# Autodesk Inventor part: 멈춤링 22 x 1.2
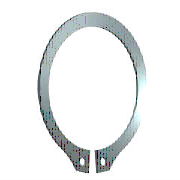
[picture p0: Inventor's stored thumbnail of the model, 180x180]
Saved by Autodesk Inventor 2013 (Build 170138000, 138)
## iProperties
IsCustomPart: 0
Company: 한국ATC센터
Created: 2014-07
Part Number: 멈춤링 22 x 1.2
Material: Steel, Mild
Description: 리테이닝 링(C형)
Document SubType Name: Modeling
Standard: KS B 1336
Designer: KYOUNG IL JANG
Standards Organization: KS
Language: ko-KR
Size Designation: 22 x 1.2
Categories: <MemberInstance><Categories><Category DisplayName="샤프트 부품" InternalName="7f7aeb1f-a693-4053-b835-cee3144e0d98" Mnemonic="SHFT"><Category DisplayName="써클립" Inter
Density: 1 g/cm^3
Author: KYOUNG IL JANG
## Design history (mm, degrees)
sketch "스케치1"
  geometry: L1 (-6, 0)-(6, 0) reference; L2 (0, 20.189)-(0, -80.536) reference; L3 (-48.09, 0)-(48.09, 0) reference; L4 (-0.5, -21.488)-(-0.5, -25.588); L5 (-0.5, -6.54)-(-0.5, -13.29); L6 (-2.795, 2.7)-(3.672, 2.7); L7 (0.5, -6.54)-(0.5, -13.29); L8 (0.5, -21.488)-(0.5, -25.588); C1 r 1 at (-2, -23.437); C2 r 1 at (2, -23.437); A1 r 10.5 centre (0, -11) between (0.5, -21.488) and (-0.5, -21.488); A2 r 13.025 centre (0, -10.325) between (5.149, -22.289) and (-5.149, -22.289); A3 r 14.597 centre (0, -11) between (-2.318, -25.411) and (-0.5, -25.588); A4 r 2 centre (-2, -23.437) between (-3.97, -23.781) and (-2.318, -25.411); A5 r 2 centre (-5.94, -24.126) between (-3.97, -23.781) and (-5.149, -22.289); A6 r 2 centre (5.94, -24.126) between (5.149, -22.289) and (3.97, -23.781); A7 r 2 centre (2, -23.437) between (2.318, -25.411) and (3.97, -23.781); A8 r 14.597 centre (0, -11) between (0.5, -25.588) and (2.318, -25.411)
  constraints: 16 point on circle, 12 end point, 10 centre point, 9 symmetric about line, 5 point on line, 4 tangent, 3 coincident, 2 horizontal, 1 perpendicular, 1 vertical, 5 other
  dimensions: "d0" = 21 diameter of A1 (= ND); "d1" = 4.1 distance of L4.end L4.start (= SRB2); "d6" = 0.5 distance between parallel lines of L2 L5 (= 0.25 x SD5); "d7" = 2.7 distance between parallel lines of L6 L3 (= SRB1); "d8" = 0.675 distance of A1.centre A2.centre (= 0.25 x SRB1); "d9" = 2 radius of A4 (= SD5); "d10" = 2 radius of A5 (= SD5); "d11" = 1.5 distance from line of L4 A4.centre (= 0.75 x SD5); "d12" = 2 diameter of C1 (= SD5); "d13" = 2 diameter of C2 (= SD5); "d14" = 11 distance from line of A1.centre L1 (= 0.5 x WD)
extrude "본체" new body sketch "스케치1" distance "d2" = 1.2 (= SD); taper "d3" = 0 deg
workaxis "Work Axis1"
workplane "Work Plane1"
body "Solid1"
other parameters: "WD" = 22 (= WDMIN) [user parameter; used in 1 equation term], "SD" = 1.2 [user parameter; used in 1 equation term], "SRB1" = 2.7 [user parameter; used in 2 equation terms], "ND" = 21 [user parameter; used in 1 equation term], "SRB2" = 4.1 [user parameter; used in 1 equation term], "SD5" = 2 [user parameter; used in 6 equation terms], "d15" = 0, "d16" = 0, "d17" = 0, "d41" = 0, "d42" = 0, "WDMIN" = 22 [user parameter; used in 1 equation term], "SD3" = 20.5 [user parameter], "WDMAX" = 24 [user parameter]
